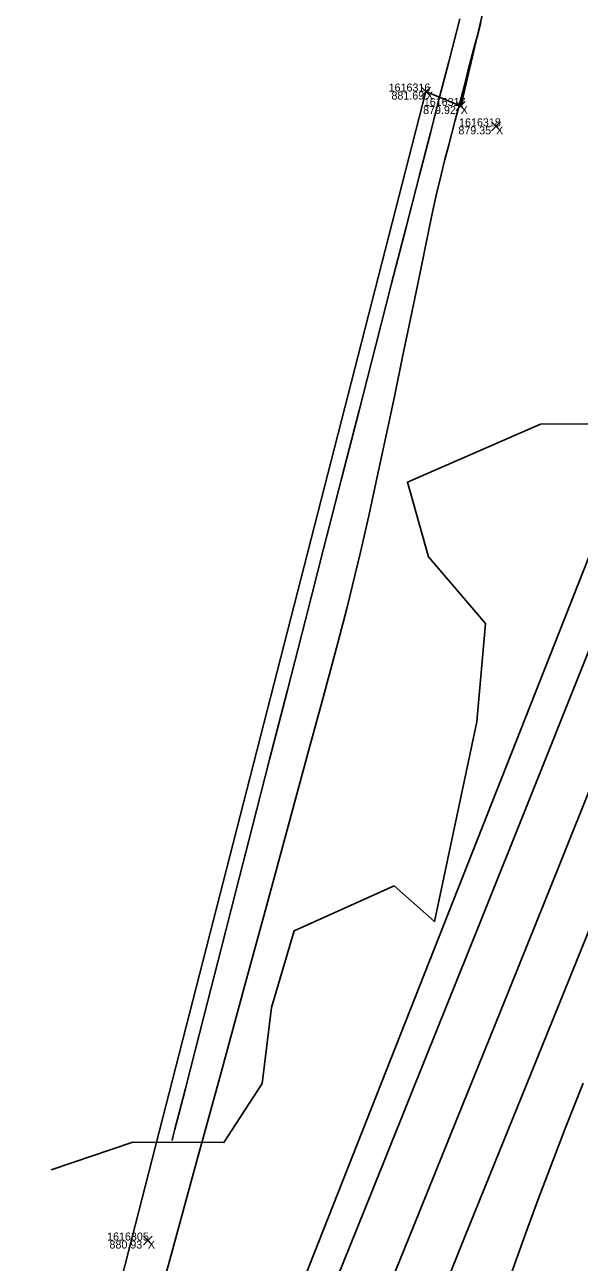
# Model space of a CAD drawing. Extents: x 1957117 to 1971063, y 701601 to 715861.
# Drawn here: x 1963352 to 1963376.2, y 706387.5 to 706441.6 of the extents above; entities that cross this region are included whole.
import ezdxf

# ---------------------------------------------------------------- set-up
doc = ezdxf.new("R2010")
doc.units = 0
for name, color, linetype in [('AP_X_Lights', 7, 'Continuous'), ('DT_X_Break_Line', 7, 'Continuous'), ('DT_X_Contour_Major', 7, 'Continuous'), ('DT_X_Contour_Minor', 7, 'Continuous'), ('DT_X_TIN_Hull', 7, 'Continuous'), ('HY_X_Water_Edge', 7, 'Continuous'), ('PV_P_Shoulder', 7, 'Continuous'), ('RS_Raster1', 7, 'Continuous'), ('SC_Scratch1', 7, 'Continuous'), ('SC_Shading5', 7, 'Continuous'), ('VG_X_Tree_Line_Rt', 7, 'Continuous')]:
    doc.layers.add(name, color=color, linetype=linetype)

msp = doc.modelspace()

# ---------------------------------------------------------------- linework, layer by layer
at = {"layer": 'AP_X_Lights'}
for p, q in [((1963369.349, 706438.485), (1963369.737, 706438.875)), ((1963369.349, 706438.875), (1963369.737, 706438.485)), ((1963370.866, 706437.853), (1963371.254, 706438.243)), ((1963370.866, 706438.243), (1963371.254, 706437.853)), ((1963372.411, 706436.962), (1963372.799, 706437.352)), ((1963372.411, 706437.352), (1963372.799, 706436.962)), ((1963357.186, 706388.242), (1963357.574, 706388.632)), ((1963357.186, 706388.632), (1963357.574, 706388.242))]:
    msp.add_line(p, q, dxfattribs=at)
at = {"layer": 'DT_X_Break_Line'}
msp.add_lwpolyline([(1963218.329, 705756.178), (1963229.265, 705808.356), (1963234.8, 705853.147), (1963240.079, 705903.468), (1963258.033, 705954.684), (1963270.287, 705999.321), (1963276.323, 706049.345), (1963291.502, 706096.678), (1963290.138, 706117.655), (1963319.921, 706191.295), (1963330.374, 706242.631), (1963344.413, 706289.409), (1963345.772, 706340.009), (1963383.117, 706434.704), (1963392.11, 706487.426), (1963408.164, 706535.687), (1963423.633, 706582.721), (1963435.242, 706630.63), (1963443.084, 706680.696), (1963464.732, 706726.815), (1963480.654, 706774.214), (1963508.465, 706799.669), (1963511.002, 706809.48)], dxfattribs=at)
at = {"layer": 'DT_X_Contour_Major'}
for points in [[(1963387.31, 706442.991), (1963386.479, 706440.327), (1963385.732, 706437.97), (1963385.082, 706435.973), (1963384.545, 706434.39), (1963383.905, 706432.647), (1963382.92, 706430.067), (1963381.625, 706426.744), (1963380.061, 706422.771), (1963378.264, 706418.242), (1963376.274, 706413.248), (1963374.129, 706407.883), (1963371.866, 706402.241), (1963369.524, 706396.415), (1963367.142, 706390.496), (1963364.757, 706384.58)], [(1963387.31, 706442.991), (1963386.479, 706440.327), (1963385.732, 706437.97), (1963385.082, 706435.973), (1963384.545, 706434.39), (1963383.905, 706432.647), (1963382.92, 706430.067), (1963381.625, 706426.744), (1963380.061, 706422.771), (1963378.264, 706418.242), (1963376.274, 706413.248), (1963374.129, 706407.883), (1963371.866, 706402.241), (1963369.524, 706396.415), (1963367.142, 706390.496), (1963364.757, 706384.58)], [(1963371.942, 706441.686), (1963371.803, 706441.18), (1963371.638, 706440.568), (1963371.506, 706440.071), (1963371.392, 706439.629), (1963371.279, 706439.188), (1963371.152, 706438.689), (1963370.994, 706438.075), (1963370.826, 706437.433), (1963370.671, 706436.853), (1963370.522, 706436.292), (1963370.369, 706435.704), (1963370.204, 706435.045), (1963370.018, 706434.27), (1963369.887, 706433.679), (1963369.698, 706432.785), (1963369.46, 706431.633), (1963369.179, 706430.268), (1963368.864, 706428.735), (1963368.522, 706427.08), (1963368.161, 706425.346), (1963367.788, 706423.581), (1963367.412, 706421.827), (1963367.039, 706420.131), (1963366.677, 706418.538), (1963366.335, 706417.092), (1963366.06, 706416.01), (1963365.624, 706414.355), (1963365.045, 706412.187), (1963364.338, 706409.568), (1963363.521, 706406.557), (1963362.611, 706403.216), (1963361.625, 706399.605), (1963360.58, 706395.785), (1963359.492, 706391.816), (1963358.379, 706387.759), (1963357.256, 706383.674)], [(1963371.942, 706441.686), (1963371.803, 706441.18), (1963371.638, 706440.568), (1963371.506, 706440.071), (1963371.392, 706439.629), (1963371.279, 706439.188), (1963371.152, 706438.689), (1963370.994, 706438.075), (1963370.826, 706437.433), (1963370.671, 706436.853), (1963370.522, 706436.292), (1963370.369, 706435.704), (1963370.204, 706435.045), (1963370.018, 706434.27), (1963369.887, 706433.679), (1963369.698, 706432.785), (1963369.46, 706431.633), (1963369.179, 706430.268), (1963368.864, 706428.735), (1963368.522, 706427.08), (1963368.161, 706425.346), (1963367.788, 706423.581), (1963367.412, 706421.827), (1963367.039, 706420.131), (1963366.677, 706418.538), (1963366.335, 706417.092), (1963366.06, 706416.01), (1963365.624, 706414.355), (1963365.045, 706412.187), (1963364.338, 706409.568), (1963363.521, 706406.557), (1963362.611, 706403.216), (1963361.625, 706399.605), (1963360.58, 706395.785), (1963359.492, 706391.816), (1963358.379, 706387.759), (1963357.256, 706383.674)]]:
    msp.add_lwpolyline(points, dxfattribs=at)
at = {"layer": 'DT_X_Contour_Minor'}
for points in [[(1963390.055, 706443.837), (1963389.3, 706441.399), (1963388.592, 706439.145), (1963387.942, 706437.114), (1963387.362, 706435.346), (1963386.862, 706433.88), (1963386.308, 706432.363), (1963385.488, 706430.214), (1963384.431, 706427.5), (1963383.166, 706424.291), (1963381.721, 706420.655), (1963380.126, 706416.662), (1963378.409, 706412.381), (1963376.598, 706407.88), (1963374.722, 706403.228), (1963372.81, 706398.494), (1963370.891, 706393.747), (1963368.993, 706389.056), (1963367.145, 706384.49)], [(1963390.055, 706443.837), (1963389.3, 706441.399), (1963388.592, 706439.145), (1963387.942, 706437.114), (1963387.362, 706435.346), (1963386.862, 706433.88), (1963386.308, 706432.363), (1963385.488, 706430.214), (1963384.431, 706427.5), (1963383.166, 706424.291), (1963381.721, 706420.655), (1963380.126, 706416.662), (1963378.409, 706412.381), (1963376.598, 706407.88), (1963374.722, 706403.228), (1963372.81, 706398.494), (1963370.891, 706393.747), (1963368.993, 706389.056), (1963367.145, 706384.49)], [(1963392.079, 706442.364), (1963391.421, 706440.247), (1963390.794, 706438.257), (1963390.205, 706436.427), (1963389.664, 706434.787), (1963389.18, 706433.371), (1963388.711, 706432.082), (1963388.05, 706430.344), (1963387.217, 706428.203), (1963386.233, 706425.709), (1963385.119, 706422.908), (1963383.893, 706419.848), (1963382.577, 706416.578), (1963381.192, 706413.144), (1963379.756, 706409.596), (1963378.291, 706405.981), (1963376.816, 706402.346), (1963375.352, 706398.74), (1963373.92, 706395.21), (1963372.539, 706391.804), (1963371.23, 706388.571), (1963370.013, 706385.557)], [(1963392.079, 706442.364), (1963391.421, 706440.247), (1963390.794, 706438.257), (1963390.205, 706436.427), (1963389.664, 706434.787), (1963389.18, 706433.371), (1963388.711, 706432.082), (1963388.05, 706430.344), (1963387.217, 706428.203), (1963386.233, 706425.709), (1963385.119, 706422.908), (1963383.893, 706419.848), (1963382.577, 706416.578), (1963381.192, 706413.144), (1963379.756, 706409.596), (1963378.291, 706405.981), (1963376.816, 706402.346), (1963375.352, 706398.74), (1963373.92, 706395.21), (1963372.539, 706391.804), (1963371.23, 706388.571), (1963370.013, 706385.557)], [(1963358.438, 706392.806), (1963358.476, 706392.955), (1963358.566, 706393.308), (1963358.736, 706393.969), (1963359.02, 706395.079), (1963359.462, 706396.803), (1963359.988, 706398.858), (1963360.587, 706401.198), (1963361.247, 706403.778), (1963361.958, 706406.552), (1963362.706, 706409.475), (1963363.482, 706412.501), (1963364.272, 706415.585), (1963365.065, 706418.681), (1963365.85, 706421.744), (1963366.615, 706424.728), (1963367.349, 706427.588), (1963368.039, 706430.279), (1963368.675, 706432.754), (1963369.244, 706434.968), (1963369.735, 706436.876), (1963370.137, 706438.433), (1963370.537, 706439.979), (1963371.024, 706441.858)], [(1963358.438, 706392.806), (1963358.476, 706392.955), (1963358.566, 706393.308), (1963358.736, 706393.969), (1963359.02, 706395.079), (1963359.462, 706396.803), (1963359.988, 706398.858), (1963360.587, 706401.198), (1963361.247, 706403.778), (1963361.958, 706406.552), (1963362.706, 706409.475), (1963363.482, 706412.501), (1963364.272, 706415.585), (1963365.065, 706418.681), (1963365.85, 706421.744), (1963366.615, 706424.728), (1963367.349, 706427.588), (1963368.039, 706430.279), (1963368.675, 706432.754), (1963369.244, 706434.968), (1963369.735, 706436.876), (1963370.137, 706438.433), (1963370.537, 706439.979), (1963371.024, 706441.858)], [(1963376.416, 706395.322), (1963375.633, 706393.337), (1963374.967, 706391.618), (1963374.435, 706390.203), (1963373.898, 706388.73), (1963373.267, 706386.975)], [(1963376.416, 706395.322), (1963375.633, 706393.337), (1963374.967, 706391.618), (1963374.435, 706390.203), (1963373.898, 706388.73), (1963373.267, 706386.975)]]:
    msp.add_lwpolyline(points, dxfattribs=at)
at = {"layer": 'DT_X_TIN_Hull'}
msp.add_lwpolyline([(1963495.509, 706817.37), (1963480.654, 706774.214), (1963464.732, 706726.815), (1963443.084, 706680.696), (1963439.989, 706681.954), (1963422.341, 706634.767), (1963409.759, 706587.541), (1963383.299, 706489.662), (1963371.06, 706438.048), (1963369.543, 706438.68), (1963344.28, 706340.158), (1963318.949, 706243.571), (1963307.297, 706195.415), (1963288.342, 706117.136), (1963272.445, 706050.395), (1963261.075, 706002.095), (1963254.734, 705951.873), (1963238.207, 705904.757)], dxfattribs=at)
at = {"layer": 'HY_X_Water_Edge'}
msp.add_spline([(1963191.723, 701994.048), (1963062.047, 702441.167), (1962863.491, 703169.356), (1962827.53, 703438.691), (1962823.213, 703537.412), (1962817.962, 703593.874), (1962817.97, 703697.316), (1962828.582, 703804.235), (1962836.461, 703844.734), (1962850.687, 703896.004), (1962867.251, 703938.846), (1962873.848, 703992.355), (1962884.135, 704091.371), (1962891.241, 704140.854), (1962897.382, 704180.529), (1962905.467, 704230.979), (1962943.949, 704328.022), (1962948.537, 704378.842), (1962964.114, 704426.264), (1963004.885, 704570.73), (1963042.054, 704716.522), (1963062.038, 704814.417), (1963072.171, 704860.237), (1963090.023, 704956.798), (1963107.066, 705031.783), (1963133.773, 705105.742), (1963148.685, 705206.74), (1963175.48, 705301.059), (1963191.635, 705353.417), (1963210.988, 705447.286), (1963219.532, 705497.27), (1963230.124, 705549.475), (1963251.052, 705591.159), (1963275.289, 705693.429), (1963292.982, 705784.032), (1963302.841, 705839.645), (1963335.126, 705936.766), (1963359.752, 706046.75), (1963389.133, 706177.299), (1963417.827, 706273.456), (1963475.868, 706451.902), (1963533.782, 706640.53), (1963553.86, 706696.984), (1963580.184, 706715.425), (1963609.172, 706718.73), (1963617.062, 706714.691), (1963619.447, 706694.678), (1963564.282, 706533.07), (1963531.853, 706395.229), (1963434.4, 706006.96), (1963354.09, 705679.186), (1963237.513, 705206.07), (1963167.369, 704892.962), (1963059.145, 704434.176), (1962907.914, 703908.742), (1962877.458, 703703.326), (1962898.357, 703412.121), (1962942.65, 703052.267), (1963048.963, 702674.866), (1963191.468, 702189.666), (1963245.396, 702019.832)], degree=3, dxfattribs=at)
at = {"layer": 'SC_Shading5'}
for points in [[(1963026.912, 704294.121), (1963138.818, 704737.794), (1963251.679, 705213.963), (1963374.306, 705730.111), (1963454.783, 706045.593), (1963517.244, 706296.713), (1963562.763, 706479.256), (1963580.13, 706553.799), (1963589.678, 706586.994)], [(1963609.915, 706579.703), (1963587.283, 706499.153), (1963552.056, 706354.005), (1963480.911, 706069.234), (1963357.401, 705576.869), (1963272.751, 705226.931), (1963210.247, 704956.481), (1963044.97, 704288.881)]]:
    msp.add_spline(points, degree=3, dxfattribs=at)
at = {"layer": 'VG_X_Tree_Line_Rt'}
msp.add_lwpolyline([(1963391.578, 706442.64), (1963388.518, 706439.683), (1963390.025, 706434.575), (1963392.132, 706431.605), (1963391.183, 706427.666), (1963388.266, 706426.908), (1963382.725, 706424.54), (1963378.691, 706424.157), (1963374.546, 706424.135), (1963368.734, 706421.595), (1963369.647, 706418.336), (1963372.15, 706415.416), (1963371.765, 706411.117), (1963369.914, 706402.383), (1963369.914, 706402.383), (1963368.152, 706403.945), (1963363.777, 706401.976), (1963362.785, 706398.627), (1963362.38, 706395.307), (1963360.703, 706392.722), (1963356.726, 706392.741), (1963353.144, 706391.532)], dxfattribs=at)

# ---------------------------------------------------------------- texts
at = {"layer": 'PV_P_Shoulder'}
for s, p in [('881.69', (1963368.033, 706438.33)), ('879.92', (1963369.418, 706437.698)), ('879.35', (1963370.96, 706436.807)), ('880.93', (1963355.702, 706388.087))]:
    msp.add_text(s, height=0.35, dxfattribs=at).set_placement(p)
at = {"layer": 'RS_Raster1'}
for s, p in [('1616316', (1963367.909, 706438.68)), ('1616317', (1963369.448, 706438.048)), ('1616318', (1963370.991, 706437.157)), ('1616305', (1963355.597, 706388.437))]:
    msp.add_text(s, height=0.35, dxfattribs=at).set_placement(p)
at = {"layer": 'SC_Scratch1'}
for p in [(1963369.543, 706438.33), (1963371.06, 706437.698), (1963372.605, 706436.807), (1963357.38, 706388.087)]:
    msp.add_text('X', height=0.35, dxfattribs=at).set_placement(p)

doc.saveas('drawing.dxf')
